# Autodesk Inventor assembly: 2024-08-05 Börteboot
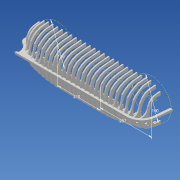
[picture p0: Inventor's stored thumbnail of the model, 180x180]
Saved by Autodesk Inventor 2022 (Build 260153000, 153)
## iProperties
Created: 2024-08
Part Number: 2024-08-05 Börteboot
Document SubType Name: Assembly
Designer: i3meg
Author: i3meg
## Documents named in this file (3)
- E:\Daten Autodesk Inventor 2022\Daten 3D Druck Vorlagen\3D Druck Vorlagen\Modellbau Fahrzeuge Schiffe\U-Boote und Schiffe\Schiffe Volker\Börte Boot\Inventor\2024-08-05 Börteboot.iam
- E:\Daten Autodesk Inventor 2022\Daten 3D Druck Vorlagen\3D Druck Vorlagen\Modellbau Fahrzeuge Schiffe\U-Boote und Schiffe\Schiffe Volker\Börte Boot\Inventor\2024-08-05 Börteboot Kiel.ipt
- E:\Daten Autodesk Inventor 2022\Daten 3D Druck Vorlagen\3D Druck Vorlagen\Modellbau Fahrzeuge Schiffe\U-Boote und Schiffe\Schiffe Volker\Börte Boot\Inventor\2024-08-05 Börteboot Spanten.ipt
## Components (2 placed, 2 different names)
1. 2024-08-05 Börteboot Kiel:1 — Passend:2, Passend:3, Passend:4
2. 2024-08-05 Börteboot Spanten:1 — Passend:2, Passend:3, Passend:4
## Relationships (3: Mate 3)
- Passend:2 [Mate]: 2024-08-05 Börteboot Kiel:1 ↔ 2024-08-05 Börteboot Spanten:1
- Passend:3 [Mate]: 2024-08-05 Börteboot Kiel:1 ↔ 2024-08-05 Börteboot Spanten:1
- Passend:4 [Mate]: 2024-08-05 Börteboot Kiel:1 ↔ 2024-08-05 Börteboot Spanten:1
